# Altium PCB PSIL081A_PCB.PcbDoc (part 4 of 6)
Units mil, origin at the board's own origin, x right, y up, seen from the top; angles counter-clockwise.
Board outline 14000 x 8000 mil, 10 copper layers (Top Layer, Signal Layer 1, Signal Layer 2, Signal Layer 3, Signal Layer 4, Signal Layer 5, Signal Layer 6, Signal Layer 7, Signal Layer 8, Bottom Layer), stack 60.9 mil thick; 433 components, 510 nets, 1716 pads, 590 vias.
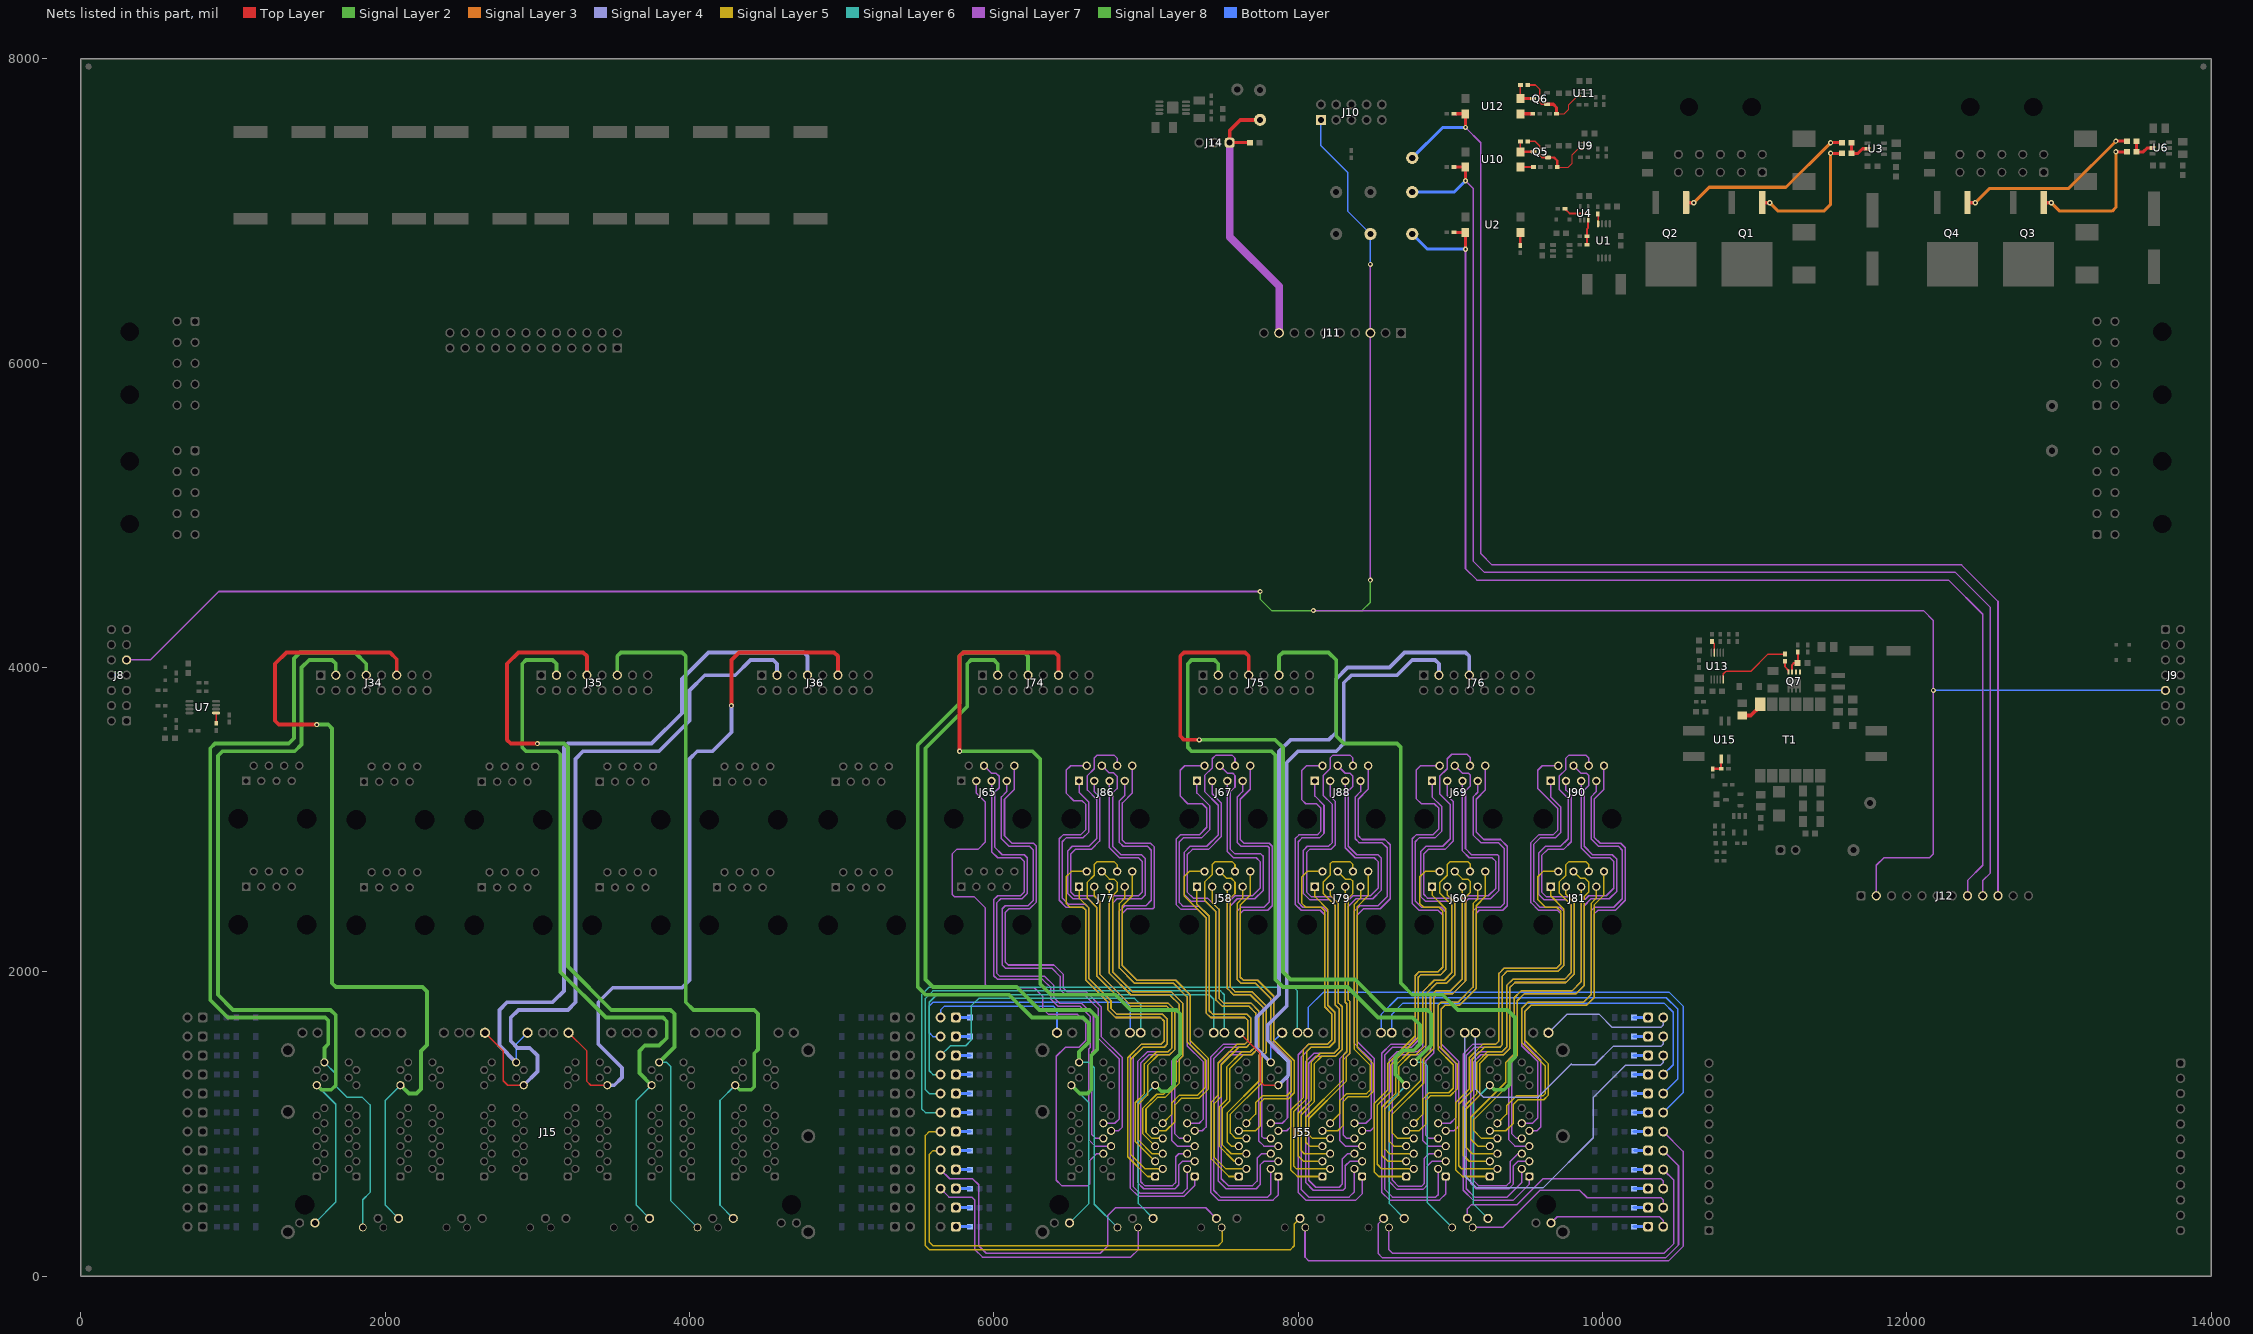
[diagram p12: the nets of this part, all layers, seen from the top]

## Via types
v1: diameter 34, hole 16, Top Layer to Bottom Layer, 429 vias
v2: diameter 26, hole 8, Top Layer to Bottom Layer, 156 vias
v3: diameter 19.68, hole 7.87, Top Layer to Bottom Layer, 5 vias

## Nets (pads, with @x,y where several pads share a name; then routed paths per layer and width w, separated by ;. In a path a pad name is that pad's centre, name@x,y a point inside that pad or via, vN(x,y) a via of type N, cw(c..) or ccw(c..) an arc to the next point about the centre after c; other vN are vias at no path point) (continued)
NetJ55_B4: J55.B4 J65.3 | length 4186.6
  Signal Layer 7 w10: J65.3@5885,3255 5885,3175 5945,3115 5945,2855 5895,2805 5755,2805 5725,2775 5725,2510 5740,2495 5870,2495 5945,2420 5945,1915 5965,1895 6265,1895 6320,1840 6320,1760 6360,1720 6550,1720 6605,1665 6605,1550 6560,1505 6470,1505 6410,1445 6410,630 6445,595 6620,595 6630,605 6630,760 6674.96,804.96 J55.B4@6720.16,804.96
NetJ55_B5: J55.B5 J65.5 | length 3394.1
  Signal Layer 7 w10: J65.5@5985,3255 5985,2790 6025,2750 6175,2750 6200,2725 6200,2525 6175,2500 6025,2500 6000,2475 6000,1975 6025,1950 6320,1950 6375,1895 6375,1820 6420,1775 6565,1775 6635,1705 6635,1504.72 6625.28,1495 6625.28,894.72 6665,855 6770.12,855 J55.B5@6770.16,854.96
NetJ55_B6: J55.B6 J65.4 | length 3445.7
  Signal Layer 7 w10: J65.4@5935,3355 5985,3305 6015,3305 6035,3285 6035,3210 6005,3180 6005,2820 6055,2770 6200,2770 6220,2750 6220,2515 6185,2480 6045,2480 6020,2455 6020,1990 6040,1970 6335,1970 6395,1910 6395,1830 6430,1795 6575,1795 6655,1715 6655,1485 6645,1475 6645,930 6670.04,904.96 J55.B6@6720.16,904.96
NetJ55_B7: J55.B7 J65.8 | length 3388
  Signal Layer 7 w10: J65.8@6135,3355 6135,3200 6070,3135 6070,2895 6120,2845 6260,2845 6280,2825 6280,2460 6235,2415 6100,2415 6075,2390 6075,2065 6095,2045 6395,2045 6455,1985 6455,1895 6480,1870 6605,1870 6705,1770 6705,1575 6845,1435 6845,980 6819.96,954.96 J55.B7@6770.16,954.96
NetJ55_B8: J55.B8 J65.7 | length 3261.5
  Signal Layer 7 w10: J65.7@6085,3255 6085,3185 6050,3150 6050,2875 6100,2825 6235,2825 6260,2800 6260,2470 6225,2435 6075,2435 6055,2415 6055,2045 6075,2025 6380,2025 6435,1970 6435,1885 6470,1850 6595,1850 6685,1760 6685,1565 6825,1425 6825,1035 6795,1005 J55.B8@6720.16,1004.96 J55.B8@6720.16,1004.96
NetJ55_B15: J55.B15 J66.2 | length 985.9
  Bottom Layer w10: J66.2@5650,1700 5650,1750 5675,1775 6390,1775 6415.04,1749.96 J55.B15@6415.04,1599.84
NetJ55_B18: J55.B18 J71.2 | length 1776.2
  Bottom Layer w10: J71.2@5650,1575 5600,1575 5575,1600 5575,1775 5600,1800 6870,1800 6895,1775 J55.B18@6894.96,1599.84 J55.B18@6894.96,1599.84
NetJ55_C1: J55.C1 J77.2 | length 2888.6
  Signal Layer 5 w10: J77.2@6610,2660 6510,2660 6475,2625 6475,2450 6500,2425 6585,2425 6605,2405 6605,1945 6750,1800 6750,1750 6800,1700 7095,1700 7120,1675 7120,1545 7100,1525 6970,1525 6880,1435 6880,785 7010,655 J55.C1@7059.92,654.96 J55.C1@7059.92,654.96
NetJ55_C2: J55.C2 J77.1 | length 2606.7
  Signal Layer 5 w10: J77.1@6560,2560 6560,2485 6625,2420 6625,1955 6770,1810 6770,1760 6810,1720 7110,1720 7140,1690 7140,1525 7120,1505 6980,1505 6900,1425 6900,800 6995.04,704.96 J55.C2@7109.92,704.96
NetJ55_C3: J55.C3 J77.6 | length 2759.6
  Signal Layer 5 w10: J77.6@6810,2660 6810,2705 6790,2725 6680,2725 6660,2705 6660,2635 6615,2590 6615,2485 6675,2425 6675,1975 6875,1775 7135,1775 7170,1740 7170,1500 7145,1475 7070,1475 6990,1395 6990,1199.94 6930,1139.94 6930,884.88 J55.C3@7059.92,754.96
NetJ55_C4: J55.C4 J77.3 | length 2377.4
  Signal Layer 5 w10: J77.3@6660,2560 6660,2500 6695,2465 6695,1985 6885,1795 7145,1795 7190,1750 7190,1490 7155,1455 7080,1455 7010,1385 7010,1190 6950,1130 6950,895 7040.04,804.96 J55.C4@7109.92,804.96
NetJ55_C5: J55.C5 J77.5 | length 2203.8
  Signal Layer 5 w10: J77.5@6760,2560 6760,1990 6900,1850 7155,1850 7220,1785 7220,1465 7200,1445 7200,1280 7115,1195 7070,1195 6980,1105 6980,934.88 J55.C5@7059.92,854.96
NetJ55_C6: J55.C6 J77.4 | length 2381.5
  Signal Layer 5 w10: J77.4@6710,2660 6760,2610 6790,2610 6810,2590 6810,2530 6780,2500 6780,2000 6910,1870 7165,1870 7240,1795 7240,1445 7220,1425 7220,1270 7125,1175 7075,1175 7000,1100 7000,945 7040.04,904.96 J55.C6@7109.92,904.96
NetJ55_C7: J55.C7 J77.8 | length 2368.8
  Signal Layer 5 w10: J77.8@6910,2660 6910,2500 6845,2435 6845,2040 6940,1945 7195,1945 7290,1850 7290,1550 7410,1430 7410,1230 7350,1170 7235,1170 7190,1125 7190,1015 7129.96,954.96 J55.C7@7059.92,954.96
NetJ55_C8: J55.C8 J77.7 | length 2139.2
  Signal Layer 5 w10: J77.7@6860,2560 6860,2485 6825,2450 6825,2025 6925,1925 7180,1925 7270,1835 7270,1540 7390,1420 7390,1240 7340,1190 7220,1190 7170,1140 7170,1065.04 J55.C8@7109.92,1004.96
NetJ55_C15: J55.C15 J78.2 | length 1843.5
  Signal Layer 7 w10: J78.2@5650,575 5705,520 5855,520 5875,500 5875,175 5925,125 6900,125 6950,175 6950,317.24 J55.C15@6947.32,319.92
NetJ55_C18: J55.C18 J83.2 | length 2544.9
  Signal Layer 7 w10: J83.2@5650,700 5710,640 5860,640 5900,600 5900,200 5950,150 6700,150 6750,200 6750,400 6800,450 7392.05,450 J55.C18@7462.28,379.76
NetJ55_D1: J55.D1 J86.2 | length 4347.5
  Signal Layer 7 w10: J86.2@6610,3355 6505,3355 6475,3325 6475,3175 6525,3125 6580,3125 6605,3100 6605,2935 6570,2900 6455,2900 6430,2875 6430,2470 6475,2425 6585,2425 6605,2405 6605,1945 6750,1800 6750,1750 6800,1700 7095,1700 7120,1675 7120,1545 7100,1525 6970,1525 6895,1450 6895,580 6950,525 7250,525 7320,595 7320,654.8 J55.D1@7320.16,654.96
NetJ55_D2: J55.D2 J86.1 | length 4046.1
  Signal Layer 7 w10: J86.1@6560,3255 6560,3180 6625,3115 6625,2920 6585,2880 6475,2880 6450,2855 6450,2485 6490,2445 6600,2445 6625,2420 6625,1955 6770,1810 6770,1760 6810,1720 7110,1720 7140,1690 7140,1525 7120,1505 6980,1505 6915,1440 6915,590 6960,545 7240,545 7270.16,575.16 J55.D2@7270.16,704.96
NetJ55_D3: J55.D3 J86.6 | length 4402.5
  Signal Layer 7 w10: J86.6@6810,3355 6810,3405 6790,3425 6680,3425 6660,3405 6660,3335 6615,3290 6615,3195 6675,3135 6675,2875 6625,2825 6515,2825 6485,2795 6485,2515 6520,2480 6620,2480 6675,2425 6675,1975 6875,1775 7135,1775 7170,1740 7170,1500 7145,1475 7010,1475 6945,1410 6945,615 6985,575 7190,575 7215,600 7215,730 7240,755 7320.12,755 J55.D3@7320.16,754.96
NetJ55_D4: J55.D4 J86.3 | length 3976
  Signal Layer 7 w10: J86.3@6660,3255 6660,3185 6695,3150 6695,2860 6640,2805 6535,2805 6505,2775 6505,2525 6530,2500 6660,2500 6695,2465 6695,1985 6885,1795 7145,1795 7190,1750 7190,1490 7155,1455 7020,1455 6965.14,1400.14 6965.14,620.14 6990.28,595 7175,595 7195,615 7195,785 7214.96,804.96 J55.D4@7270.16,804.96
NetJ55_D5: J55.D5 J86.5 | length 3238.3
  Signal Layer 7 w10: J86.5@6760,3255 6760,2815 6825,2750 6950,2750 6975,2725 6975,2525 6950,2500 6785,2500 6760,2475 6760,1990 6900,1850 7155,1850 7220,1785 7220,1465 7170,1415 7170,890 7205,855 7320.12,855 J55.D5@7320.16,854.96
NetJ55_D6: J55.D6 J86.4 | length 3295.6
  Signal Layer 7 w10: J86.4@6710,3355 6755,3310 6785,3310 6810,3285 6810,3205 6780,3175 6780,2825 6835,2770 6970,2770 6995,2745 6995,2505 6970,2480 6810,2480 6780,2450 6780,2000 6910,1870 7165,1870 7240,1795 7240,1445 7190,1395 7190,935 7220.04,904.96 J55.D6@7270.16,904.96
NetJ55_D7: J55.D7 J86.8 | length 3234.5
  Signal Layer 7 w10: J86.8@6910,3355 6910,3175 6845,3110 6845,2865 6865,2845 7030,2845 7055,2820 7055,2425 7045,2415 6875,2415 6845,2385 6845,2040 6940,1945 7195,1945 7290,1850 7290,1525 7395,1420 7395,980 7369.96,954.96 J55.D7@7320.16,954.96
NetJ55_D8: J55.D8 J86.7 | length 3081.6
  Signal Layer 7 w10: J86.7@6860,3255 6860,3160 6825,3125 6825,2850 6850,2825 7010,2825 7035,2800 7035,2470 7000,2435 6860,2435 6825,2400 6825,2025 6925,1925 7180,1925 7270,1835 7270,1515 7375,1410 7375,1030 7349.96,1004.96 J55.D8@7270.16,1004.96
NetJ55_D15: J55.D15 J87.2 | length 1803.9
  Signal Layer 6 w10: J87.2@5650,1450 5715,1515 5815,1515 5850,1550 5850,1775 5900,1825 6925,1825 6965,1785 J55.D15@6965.04,1599.84 J55.D15@6965.04,1599.84
NetJ55_D18: J55.D18 J92.2 | length 2658.7
  Signal Layer 6 w10: J92.2@5650,1325 5600,1325 5575,1350 5575,1800 5625,1850 7415,1850 7445,1820 J55.D18@7444.96,1599.84 J55.D18@7444.96,1599.84
NetJ55_E1: J55.E1 J58.2 | length 2666.5
  Signal Layer 5 w10: J58.2@7385,2660 7285,2660 7250,2625 7250,2500 7395,2355 7395,1730 7425,1700 7650,1700 7670,1680 7670,1545 7650,1525 7600,1525 7475,1400 7475,1190 7430,1145 7430,770 7545,655 J55.E1@7609.92,654.96 J55.E1@7609.92,654.96
NetJ55_E2: J55.E2 J58.1 | length 2428.6
  Signal Layer 5 w10: J58.1@7335,2560 7335,2445 7415,2365 7415,1745 7440,1720 7665,1720 7690,1695 7690,1535 7660,1505 7610,1505 7495,1390 7495,1180 7450,1135 7450,780 7525.04,704.96 J55.E2@7659.92,704.96
NetJ55_E3: J55.E3 J58.6 | length 2626.5
  Signal Layer 5 w10: J58.6@7585,2660 7585,2705 7565,2725 7455,2725 7435,2705 7435,2640 7385,2590 7385,2470 7460,2395 7460,1815 7500,1775 7675,1775 7720,1730 7720,1510 7685,1475 7630,1475 7530,1375 7530,1160 7480,1110 7480,855 7580,755 J55.E3@7609.92,754.96 J55.E3@7609.92,754.96
NetJ55_E4: J55.E4 J58.3 | length 2242.8
  Signal Layer 5 w10: J58.3@7435,2560 7435,2455 7480,2410 7480,1825 7510,1795 7690,1795 7740,1745 7740,1500 7695,1455 7640.6,1455 7550.6,1365 7550.6,1150.6 7500,1100 7500,865 7560.04,804.96 J55.E4@7659.92,804.96
NetJ55_E5: J55.E5 J58.5 | length 2024.4
  Signal Layer 5 w10: J58.5@7535,2560 7535,1890 7575,1850 7685,1850 7770,1765 7770,1480 7745,1455 7745,1285 7535,1075 7535,880 7560,855 J55.E5@7609.92,854.96 J55.E5@7609.92,854.96
NetJ55_E6: J55.E6 J58.4 | length 2170
  Signal Layer 5 w10: J58.4@7485,2660 7530,2615 7560,2615 7585,2590 7585,2515 7555,2485 7555,1900 7585,1870 7695,1870 7790,1775 7790,1470 7765,1445 7765,1275 7555,1065 7555,940 7590.04,904.96 J55.E6@7659.92,904.96
NetJ55_E7: J55.E7 J58.8 | length 2244.1
  Signal Layer 5 w10: J55.E7@7609.92,954.96 7719.96,954.96 7750,985 7750,1140 7775,1165 7935,1165 7975,1205 7975,1415 7840,1550 7840,1840 7735,1945 7640,1945 7620,1965 7620,2440 7685,2505 J58.8@7685,2660
NetJ55_E8: J55.E8 J58.7 | length 1988.2
  Signal Layer 5 w10: J58.7@7635,2560 7635,2485 7600,2450 7600,1950 7625,1925 7720,1925 7820,1825 7820,1545 7955,1410 7955,1215 7925,1185 7765,1185 7720,1140 7720,1065.04 J55.E8@7659.92,1004.96
NetJ55_E15: J55.E15 J59.2 | length 2702.1
  Signal Layer 5 w10: J59.2@5650,825 5600,825 5575,800 5575,225 5600,200 7475,200 7500,225 7500,317.24 J55.E15@7497.32,319.92
NetJ55_E18: J55.E18 J63.2 | length 3476.3
  Signal Layer 5 w10: J63.2@5650,950 5575,950 5550,925 5550,200 5575,175 7950,175 7975,200 7975,342.48 J55.E18@8012.28,379.76
NetJ55_F1: J55.F1 J67.2 | length 4406.3
  Signal Layer 7 w10: J67.2@7385,3355 7255,3355 7225,3325 7225,3155 7275,3105 7370,3105 7400,3075 7400,2950 7350,2900 7225,2900 7200,2875 7200,2440 7230,2410 7340,2410 7395,2355 7395,1730 7425,1700 7650,1700 7670,1680 7670,1545 7650,1525 7510,1525 7425,1440 7425,550 7475,500 7835,500 7870,535 7870,654.8 J55.F1@7870.16,654.96
NetJ55_F2: J55.F2 J67.1 | length 4016.8
  Signal Layer 7 w10: J67.1@7335,3255 7335,3175 7420,3090 7420,2935 7365,2880 7245,2880 7220,2855 7220,2455 7245,2430 7350,2430 7415,2365 7415,1745 7440,1720 7665,1720 7690,1695 7690,1535 7660,1505 7520,1505 7445,1430 7445,565 7490,520 7800,520 7820.16,540.16 J55.F2@7820.16,704.96
NetJ55_F3: J55.F3 J67.6 | length 4312.2
  Signal Layer 7 w10: J67.6@7585,3355 7585,3405 7565,3425 7460,3425 7435,3400 7435,3340 7385,3290 7385,3185 7475,3095 7475,2900 7400,2825 7290,2825 7250,2785 7250,2510 7295,2465 7390,2465 7460,2395 7460,1815 7500,1775 7675,1775 7720,1730 7720,1510 7685,1475 7545,1475 7475,1405 7475,625 7525,575 7725,575 7750,600 7750,730 7775,755 7870.12,755 J55.F3@7870.16,754.96
NetJ55_F4: J55.F4 J67.3 | length 3852.5
  Signal Layer 7 w10: J67.3@7435,3255 7435,3170 7495,3110 7495,2890 7410,2805 7305,2805 7270,2770 7270,2525 7310,2485 7405,2485 7480,2410 7480,1825 7510,1795 7690,1795 7740,1745 7740,1500 7695,1455 7555,1455 7495,1395 7495,640 7540,595 7700,595 7730,625 7730,775 7759.96,804.96 J55.F4@7820.16,804.96
NetJ55_F5: J55.F5 J67.5 | length 3017.2
  Signal Layer 7 w10: J67.5@7535,3255 7535,2790 7575,2750 7725,2750 7750,2725 7750,2550 7700,2500 7585,2500 7535,2450 7535,1890 7575,1850 7685,1850 7770,1765 7770,1480 7740,1450 7740,890 7775,855 7870.12,855 J55.F5@7870.16,854.96
NetJ55_F6: J55.F6 J67.4 | length 3095
  Signal Layer 7 w10: J67.4@7485,3355 7535,3305 7570,3305 7585,3290 7585,3215 7555,3185 7555,2805 7585,2775 7755,2775 7770,2760 7770,2535 7715,2480 7600,2480 7555,2435 7555,1900 7585,1870 7695,1870 7790,1775 7790,1470 7760,1440 7760,920 7775.04,904.96 J55.F6@7820.16,904.96
NetJ55_F7: J55.F7 J67.8 | length 3048.8
  Signal Layer 7 w10: J67.8@7685,3355 7685,3200 7620,3135 7620,2870 7645,2845 7810,2845 7830,2825 7830,2435 7800,2405 7640,2405 7620,2385 7620,1965 7640,1945 7735,1945 7840,1840 7840,1530 7950,1420 7950,980 7924.96,954.96 J55.F7@7870.16,954.96
NetJ55_F8: J55.F8 J67.7 | length 2910.5
  Signal Layer 7 w10: J67.7@7635,3255 7635,3185 7600,3150 7600,2850 7625,2825 7800,2825 7810,2815 7810,2460 7775,2425 7625,2425 7600,2400 7600,1950 7625,1925 7720,1925 7820,1825 7820,1515 7930,1405 7930,1040 7895,1005 J55.F8@7820.16,1004.96 J55.F8@7820.16,1004.96
NetJ55_F15: J55.F15 J68.2 | length 2956.6
  Signal Layer 6 w10: J68.2@5650,1200 5575,1200 5550,1225 5550,1825 5600,1875 7490,1875 7515.04,1849.96 J55.F15@7515.04,1599.84
NetJ55_F18: J55.F18 J72.2 | length 3661.6
  Signal Layer 6 w10: J72.2@5650,1075 5550,1075 5525,1100 5525,1850 5575,1900 7970,1900 7995,1875 J55.F18@7994.96,1599.84 J55.F18@7994.96,1599.84
NetJ55_G1: J55.G1 J79.2 | length 2627.3
  Signal Layer 5 w10: J55.G1@8159.92,654.96 J55.G1@8159.92,654.96 7995,655 7950,700 7950,1090 8035,1175 8035,1490 8070,1525 8194.72,1525 8220,1550.28 8220,1725 8175,1770 8175,2400 8150,2425 8050,2425 8025,2450 8025,2625 8060,2660 J79.2@8160,2660
NetJ55_G2: J55.G2 J79.1 | length 2319.2
  Signal Layer 5 w10: J79.1@8110,2560 8110,2495 8195,2410 8195,1780 8240,1735 8240,1540 8205,1505 8085,1505 8055,1475 8055,1165 7970,1080 7970,725 7990.04,704.96 J55.G2@8209.92,704.96
NetJ55_G3: J55.G3 J79.6 | length 2530.6
  Signal Layer 5 w10: J55.G3@8159.92,754.96 J55.G3@8159.92,754.96 8035,755 8000,790 8000,1070 8085,1155 8085,1405 8145,1465 8235,1465 8270,1500 8270,1755 8245,1780 8245,2435 8165,2515 8165,2590 8210,2635 8210,2710 8225,2725 8340,2725 8360,2705 J79.6@8360,2660
NetJ55_G4: J55.G4 J79.3 | length 2130.9
  Signal Layer 5 w10: J55.G4@8209.92,804.96 8040.04,804.96 8020,825 8020,1060 8105,1145 8105,1395 8155,1445 8245,1445 8290,1490 8290,1770 8265,1795 8265,2450 8210,2505 J79.3@8210,2560
NetJ55_G5: J55.G5 J79.5 | length 1916.3
  Signal Layer 5 w10: J55.G5@8159.92,854.96 J55.G5@8159.92,854.96 8075,855 8050,880 8050,1045 8295,1290 8295,1450 8320,1475 8320,1790 8310,1800 J79.5@8310,2560
NetJ55_G6: J55.G6 J79.4 | length 2070.6
  Signal Layer 5 w10: J55.G6@8209.92,904.96 8095.04,904.96 8070,930 8070,1035 8315,1280 8315,1440 8340,1465 8340,1805 8330,1815 8330,2485 8360,2515 8360,2595 8345,2610 8310,2610 J79.4@8260,2660
NetJ55_G7: J55.G7 J79.8 | length 2051.1
  Signal Layer 5 w10: J55.G7@8159.92,954.96 8159.96,955 8260,955 8295,990 8295,1145 8330,1180 8460,1180 8495,1215 8495,1395 8390,1500 8390,2430 8460,2500 J79.8@8460,2660
NetJ55_G8: J55.G8 J79.7 | length 1801.1
  Signal Layer 5 w10: J55.G8@8209.92,1004.96 8275,1070.04 8275,1155 8320,1200 8450,1200 8475,1225 8475,1385 8370,1490 8370,2445 8410,2485 J79.7@8410,2560
NetJ55_G15: J55.G15 J80.2 | length 3539.4
  Signal Layer 7 w10: J55.G15@8047.32,319.92 8045,317.6 8045,125 8070,100 10435,100 10530,195 10530,820 J80.2@10400,950
NetJ55_G18: J55.G18 J84.2 | length 2929.3
  Signal Layer 7 w10: J55.G18@8562.28,379.76 8525,342.48 8525,150 8555,120 10415,120 10500,205 10500,725 J84.2@10400,825
NetJ55_H1: J55.H1 J88.2 | length 4065
  Signal Layer 7 w10: J88.2@8160,3355 8055,3355 8025,3325 8025,3130 8050,3105 8120,3105 8150,3075 8150,2925 8125,2900 8005,2900 7980,2875 7980,2445 8020,2405 8145,2405 8175,2375 8175,1770 8220,1725 8220,1550.28 8194.72,1525 8070,1525 8000,1455 8000,550 8050,500 8380,500 8420,540 8420,654.8 J55.H1@8420.16,654.96
NetJ55_H2: J55.H2 J88.1 | length 3722.8
  Signal Layer 7 w10: J88.1@8110,3255 8110,3155 8170,3095 8170,2910 8140,2880 8025,2880 8000,2855 8000,2455 8030,2425 8165,2425 8195,2395 8195,1780 8240,1735 8240,1540 8205,1505 8085,1505 8020,1440 8020,570 8070,520 8335,520 8370.16,555.16 J55.H2@8370.16,704.96
NetJ55_H3: J55.H3 J88.6 | length 4106.1
  Signal Layer 7 w10: J88.6@8360,3355 8360,3405 8340,3425 8230,3425 8210,3405 8210,3335 8165,3290 8165,3160 8225,3100 8225,2850 8200,2825 8060,2825 8035,2800 8035,2515 8075,2475 8205,2475 8245,2435 8245,1780 8270,1755 8270,1500 8235,1465 8105,1465 8050,1410 8050,615 8100,565 8295,565 8310,580 8310,725 8340,755 8420.12,755 J55.H3@8420.16,754.96
NetJ55_H4: J55.H4 J88.3 | length 3650.5
  Signal Layer 7 w10: J88.3@8210,3255 8210,3155 8245,3120 8245,2835 8215,2805 8075,2805 8055,2785 8055,2525 8085,2495 8220,2495 8265,2450 8265,1795 8290,1770 8290,1490 8245,1445 8115,1445 8070,1400 8070,630 8115,585 8270,585 8290,605 8290,770 8324.96,804.96 J55.H4@8370.16,804.96
NetJ55_H5: J55.H5 J88.5 | length 2866.2
  Signal Layer 7 w10: J88.5@8310,3255 8310,2815 8375,2750 8500,2750 8525,2725 8525,2550 8475,2500 8360,2500 8310,2450 8310,1800 8320,1790 8320,1475 8275,1430 8275,890 8310,855 8420.12,855 J55.H5@8420.16,854.96
NetJ55_H6: J55.H6 J88.4 | length 2929.3
  Signal Layer 7 w10: J88.4@8260,3355 8310,3305 8340,3305 8360,3285 8360,3220 8330,3190 8330,2825 8385,2770 8525,2770 8545,2750 8545,2535 8490,2480 8380,2480 8330,2430 8330,1815 8340,1805 8340,1465 8295,1420 8295,930 8320.04,904.96 J55.H6@8370.16,904.96
NetJ55_H7: J55.H7 J88.8 | length 2866
  Signal Layer 7 w10: J55.H7@8420.16,954.96 8474.96,954.96 8500,980 8500,1430 8390,1540 8390,2375 8430,2415 8540,2415 8605,2480 8605,2835 8570,2870 8420,2870 8395,2895 8395,3135 8460,3200 J88.8@8460,3355
NetJ55_H8: J55.H8 J88.7 | length 2733.6
  Signal Layer 7 w10: J55.H8@8370.16,1004.96 8444.96,1004.96 8480,1040 8480,1420 8370,1530 8370,2400 8405,2435 8525,2435 8585,2495 8585,2815 8550,2850 8400,2850 8375,2875 8375,3150 8410,3185 J88.7@8410,3255
NetJ55_H15: J55.H15 J89.2 | length 3462.7
  Bottom Layer w10: J55.H15@8065.04,1599.84 J55.H15@8065.04,1599.84 8065,1765 8165,1865 10440,1865 10530,1775 10530,1205 J89.2@10400,1075
NetJ55_H18: J55.H18 J93.2 | length 2741.2
  Bottom Layer w10: J55.H18@8544.96,1599.84 8544.96,1719.96 8655,1830 10420,1830 10495,1755 10495,1295 J93.2@10400,1200
NetJ55_I1: J55.I1 J60.2 | length 2687.2
  Signal Layer 5 w10: J55.I1@8709.92,654.96 J55.I1@8709.92,654.96 8530,655 8500,685 8500,1135 8590,1225 8590,1400 8770,1580 8770,1975 8795,2000 8920,2000 8950,2030 8950,2400 8925,2425 8825,2425 8800,2450 8800,2625 8835,2660 J60.2@8930,2660
NetJ55_I2: J55.I2 J60.1 | length 2377.2
  Signal Layer 5 w10: J55.I2@8759.92,704.96 8550.04,704.96 8520,735 8520,1125 8610,1215 8610,1390 8790,1570 8790,1965 8805,1980 8935,1980 8970,2015 8970,2415 8880,2505 J60.1@8880,2560
NetJ55_I3: J55.I3 J60.6 | length 2601
  Signal Layer 5 w10: J55.I3@8709.92,754.96 J55.I3@8709.92,754.96 8590,755 8550,795 8550,1110 8640,1200 8640,1385 8730,1475 8760,1475 8820,1535 8820,1870 8895,1945 8960,1945 9010,1995 9010,2440 8930,2520 8930,2585 8980,2635 8980,2705 9000,2725 9115,2725 9130,2710 J60.6@9130,2660
NetJ55_I4: J55.I4 J60.3 | length 2197.2
  Signal Layer 5 w10: J55.I4@8759.92,804.96 8600.04,804.96 8570,835 8570,1100 8660,1190 8660,1375 8740,1455 8775,1455 8840,1520 8840,1855 8910,1925 8975,1925 9030,1980 9030,2455 8980,2505 J60.3@8980,2560
NetJ55_I5: J55.I5 J60.5 | length 2051.8
  Signal Layer 5 w10: J55.I5@8709.92,854.96 J55.I5@8709.92,854.96 8630,855 8600,885 8600,1080 8805,1285 8805,1440 8870,1505 8870,1840 8905,1875 9000,1875 9080,1955 J60.5@9080,2560
NetJ55_I6: J55.I6 J60.4 | length 2206.2
  Signal Layer 5 w10: J55.I6@8759.92,904.96 8655.04,904.96 8620,940 8620,1065 8825,1270 8825,1430 8890,1495 8890,1830 8915,1855 9015,1855 9100,1940 9100,2490 9130,2520 9130,2595 9115,2610 9080,2610 J60.4@9030,2660
NetJ55_I7: J55.I7 J60.8 | length 2189.1
  Signal Layer 5 w10: J55.I7@8709.92,954.96 8794.96,954.96 8840,1000 8840,1155 8870,1185 9000,1185 9045,1230 9045,1395 8940,1500 8940,1755 8965,1780 9060,1780 9170,1890 9170,2435 9230,2495 J60.8@9230,2660
NetJ55_I8: J55.I8 J60.7 | length 1952.5
  Signal Layer 5 w10: J55.I8@8759.92,1004.96 8820,1065.04 8820,1165 8860,1205 8990,1205 9020,1235 9020,1390 8920,1490 8920,1780 8940,1800 9050,1800 9150,1900 9150,2450 9180,2480 J60.7@9180,2560
NetJ55_I15: J55.I15 J61.2 | length 2572.2
  Signal Layer 7 w10: J55.I15@8597.32,319.92 8595,317.6 8595,175 8620,150 10405,150 10470,215 10470,630 J61.2@10400,700
NetJ55_I18: J55.I18 J64.2 | length 1488.3
  Signal Layer 7 w10: J55.I18@9112.28,379.76 9112.28,442.28 9140,470 9440,470 9610,640 10385,640 10400,625 J64.2@10400,575
NetJ55_J1: J55.J1 J69.2 | length 4231.8
  Signal Layer 7 w10: J69.2@8930,3355 8805,3355 8775,3325 8775,3140 8810,3105 8895,3105 8925,3075 8925,2940 8885,2900 8775,2900 8750,2875 8750,2450 8795,2405 8920,2405 8950,2375 8950,2030 8920,2000 8795,2000 8770,1975 8770,1560 8735,1525 8610,1525 8550,1465 8550,550 8600,500 8930,500 8970,540 8970,654.8 J55.J1@8970.16,654.96
NetJ55_J2: J55.J2 J69.1 | length 3866.9
  Signal Layer 7 w10: J69.1@8880,3255 8880,3150 8945,3085 8945,2925 8900,2880 8795,2880 8770,2855 8770,2465 8810,2425 8940,2425 8970,2395 8970,2015 8935,1980 8805,1980 8790,1965 8790,1550 8745,1505 8620,1505 8570,1455 8570,570 8620,520 8905,520 8920.16,535.16 J55.J2@8920.16,704.96
NetJ55_J3: J55.J3 J69.6 | length 4201.1
  Signal Layer 7 w10: J55.J3@8970.16,754.96 8970.12,755 8880,755 8850,725 8850,600 8820,570 8650,570 8600,620 8600,1425 8650,1475 8785,1475 8820,1510 8820,1870 8895,1945 8960,1945 9010,1995 9010,2440 8985,2465 8835,2465 8805,2495 8805,2790 8840,2825 8950,2825 9000,2875 9000,3100 8930,3170 8930,3285 8980,3335 8980,3400 9010,3430 9110,3430 9130,3410 J69.6@9130,3355
NetJ55_J4: J55.J4 J69.3 | length 3749.9
  Signal Layer 7 w10: J55.J4@8920.16,804.96 8859.96,804.96 8830,775 8830,610 8810,590 8660,590 8620,630 8620,1416.54 8658.46,1455 8795,1455 8840,1500 8840,1855 8910,1925 8975,1925 9030,1980 9030,2455 9000,2485 8850,2485 8825,2510 8825,2775 8855,2805 8965,2805 9020,2860 9020,3120 8980,3160 J69.3@8980,3255
NetJ55_J5: J55.J5 J69.5 | length 3048.1
  Signal Layer 7 w10: J55.J5@8970.16,854.96 8855.04,854.96 8820,890 8820,1425 8870,1475 8870,1840 8905,1875 9000,1875 9080,1955 9080,2475 9105,2500 9250,2500 9300,2550 9300,2725 9275,2750 9125,2750 9080,2795 J69.5@9080,3255
NetJ55_J6: J55.J6 J69.4 | length 3128.8
  Signal Layer 7 w10: J55.J6@8920.16,904.96 8860.04,904.96 8840,925 8840,1415 8890,1465 8890,1830 8915,1855 9015,1855 9100,1940 9100,2460 9120,2480 9265,2480 9320,2535 9320,2760 9310,2770 9140,2770 9100,2810 9100,3190 9130,3220 9130,3295 9120,3305 9080,3305 J69.4@9030,3355
NetJ55_J7: J55.J7 J69.8 | length 3015.8
  Signal Layer 7 w10: J55.J7@8970.16,954.96 9024.96,954.96 9055,985 9055,1410 8940,1525 8940,1755 8965,1780 9060,1780 9170,1890 9170,2385 9190,2405 9345,2405 9375,2435 9375,2825 9330,2870 9220,2870 9170,2920 9170,3135 9230,3195 J69.8@9230,3355
NetJ55_J8: J55.J8 J69.7 | length 2892.1
  Signal Layer 7 w10: J55.J8@8920.16,1004.96 8999.96,1004.96 9035,1040 9035,1400 8920,1515 8920,1780 8940,1800 9050,1800 9150,1900 9150,2400 9175,2425 9330,2425 9355,2450 9355,2810 9315,2850 9200,2850 9150,2900 9150,3150 9180,3180 J69.7@9180,3255
NetJ55_J15: J55.J15 J70.2 | length 2463
  Bottom Layer w10: J55.J15@8615.04,1599.84 8615.04,1719.96 8615,1720 8690,1795 10405,1795 10465,1735 10465,1390 J70.2@10400,1325
NetJ55_J18: J55.J18 J73.2 | length 2820
  Signal Layer 4 w10: J55.J18@9094.96,1599.84 9094.96,660.04 9175,580 9610,580 9940,910 9940,1175 10150,1385 10380,1385 10400,1405 J73.2@10400,1450
  Bottom Layer w10: J55.J18@9094.96,1599.84 J55.J18@9094.96,1599.84
NetJ55_K1: J55.K1 J81.2 | length 2961.8
  Signal Layer 5 w10: J55.K1@9259.92,654.96 J55.K1@9259.92,654.96 9080,655 9035,700 9035,1140 9125,1230 9125,1435 9215,1525 9300,1525 9320,1545 9320,1990 9355,2025 9700,2025 9725,2050 9725,2400 9700,2425 9625,2425 9575,2475 9575,2625 9610,2660 J81.2@9710,2660
NetJ55_K2: J55.K2 J81.1 | length 2674.1
  Signal Layer 5 w10: J55.K2@9309.92,704.96 9075.04,704.96 9055,725 9055,1130 9145,1220 9145,1425 9225,1505 9325,1505 9340,1520 9340,1970 9375,2005 9710,2005 9745,2040 9745,2415 9660,2500 J81.1@9660,2560
NetJ55_K3: J55.K3 J81.6 | length 2913.8
  Signal Layer 5 w10: J55.K3@9259.92,754.96 J55.K3@9259.92,754.96 9125,755 9085,795 9085,1110 9175,1200 9175,1405 9245,1475 9340,1475 9370,1505 9370,1910 9410,1950 9750,1950 9795,1995 9795,2440 9715,2520 9715,2590 9760,2635 9760,2705 9780,2725 9890,2725 9910,2705 J81.6@9910,2660
NetJ55_K4: J55.K4 J81.3 | length 2508.2
  Signal Layer 5 w10: J55.K4@9309.92,804.96 9145.04,804.96 9105,845 9105,1100 9195,1190 9195,1400 9250,1455 9350,1455 9390,1495 9390,1895 9425,1930 9760,1930 9815,1985 9815,2455 9760,2510 J81.3@9760,2560
NetJ55_K5: J55.K5 J81.5 | length 2300.1
  Signal Layer 5 w10: J55.K5@9259.92,854.96 J55.K5@9259.92,854.96 9180,855 9135,900 9135,1045 9365,1275 9365,1405 9420,1460 9420,1830 9465,1875 9800,1875 9860,1935 J81.5@9860,2560
NetJ55_K6: J55.K6 J81.4 | length 2451.5
  Signal Layer 5 w10: J55.K6@9309.92,904.96 9205.04,904.96 9155,955 9155,1030 9395,1270 9395,1405 9440,1450 9440,1810 9485,1855 9825,1855 9880,1910 9880,2495 9910,2525 9910,2590 9885,2615 9855,2615 J81.4@9810,2660
NetJ55_K7: J55.K7 J81.8 | length 2519.1
  Signal Layer 5 w10: J55.K7@9259.92,954.96 9364.96,954.96 9415,1005 9415,1130 9445,1160 9615,1160 9645,1190 9645,1395 9490,1550 9490,1740 9530,1780 9895,1780 9945,1830 9945,2440 10010,2505 J81.8@10010,2660
NetJ55_K8: J55.K8 J81.7 | length 2269
  Signal Layer 5 w10: J55.K8@9309.92,1004.96 9370,1065.04 9370,1120 9435,1185 9610,1185 9625,1200 9625,1380 9470,1535 9470,1760 9510,1800 9875,1800 9925,1850 9925,2450 9960,2485 J81.7@9960,2560
NetJ55_K15: J55.K15 J82.2 | length 1431.1
  Signal Layer 7 w10: J55.K15@9147.32,319.92 9344.92,319.92 9590,565 9850,565 9900,515 10385,515 10400,500 J82.2@10400,450
NetJ55_K18: J55.K18 J85.2 | length 804.3
  Signal Layer 7 w10: J55.K18@9662.68,349.84 9702.83,390 10375,390 10400,365 J85.2@10400,325
NetJ55_L1: J55.L1 J90.2 | length 4353.9
  Signal Layer 7 w10: J55.L1@9520.16,654.96 9520,654.8 9520,605 9415,500 9150,500 9085,565 9085,1460 9150,1525 9300,1525 9320,1545 9320,1990 9355,2025 9700,2025 9725,2050 9725,2385 9705,2405 9580,2405 9530,2455 9530,2850 9580,2900 9675,2900 9705,2930 9705,3075 9575,3205 9575,3325 9605,3355 J90.2@9710,3355
NetJ55_L2: J55.L2 J90.1 | length 4070.1
  Signal Layer 7 w10: J55.L2@9470.16,704.96 9470.16,615.16 9375,520 9160,520 9105,575 9105,1450 9160,1505 9325,1505 9340,1520 9340,1970 9375,2005 9710,2005 9745,2040 9745,2400 9720,2425 9590,2425 9550,2465 9550,2840 9590,2880 9690,2880 9725,2915 9725,3085 9660,3150 J90.1@9660,3255
NetJ55_L3: J55.L3 J90.6 | length 4473.3
  Signal Layer 7 w10: J55.L3@9520.16,754.96 9520.12,755 9445,755 9415,725 9415,605 9385,575 9170,575 9135,610 9135,1420 9190,1475 9340,1475 9370,1505 9370,1910 9410,1950 9750,1950 9795,1995 9795,2440 9760,2475 9615,2475 9580,2510 9580,2780 9625,2825 9725,2825 9775,2875 9775,3140 9715,3200 9715,3285 9760,3330 9760,3405 9780,3425 9890,3425 9910,3405 J90.6@9910,3355
NetJ55_L4: J55.L4 J90.3 | length 4011.9
  Signal Layer 7 w10: J55.L4@9470.16,804.96 9444.96,804.96 9395,755 9395,620 9370,595 9185,595 9155,625 9155,1410 9200,1455 9350,1455 9390,1495 9390,1895 9425,1930 9760,1930 9815,1985 9815,2455 9775,2495 9630,2495 9600,2525 9600,2765 9640,2805 9745,2805 9795,2855 9795,3160 9760,3195 J90.3@9760,3255
NetJ55_L5: J55.L5 J90.5 | length 3223.4
  Signal Layer 7 w10: J55.L5@9520.16,854.96 9520.12,855 9425,855 9385,895 9385,1425 9420,1460 9420,1830 9465,1875 9800,1875 9860,1935 9860,2450 9910,2500 10025,2500 10075,2550 10075,2725 10050,2750 9925,2750 9860,2815 J90.5@9860,3255
NetJ55_L6: J55.L6 J90.4 | length 3292.4
  Signal Layer 7 w10: J55.L6@9470.16,904.96 9435.04,904.96 9405,935 9405,1415 9440,1450 9440,1810 9485,1855 9825,1855 9880,1910 9880,2435 9925,2480 10045,2480 10095,2530 10095,2740 10065,2770 9935,2770 9880,2825 9880,3195 9910,3225 9910,3290 9895,3305 9860,3305 J90.4@9810,3355
NetJ55_L7: J55.L7 J90.8 | length 3249.2
  Signal Layer 7 w10: J55.L7@9520.16,954.96 9569.96,954.96 9595,980 9595,1420 9490,1525 9490,1740 9530,1780 9895,1780 9945,1830 9945,2380 9970,2405 10085,2405 10150,2470 10150,2815 10120,2845 9985,2845 9945,2885 9945,3135 10010,3200 J90.8@10010,3355
NetJ55_L8: J55.L8 J90.7 | length 3113.8
  Signal Layer 7 w10: J55.L8@9470.16,1004.96 9539.96,1004.96 9575,1040 9575,1410 9470,1515 9470,1760 9510,1800 9875,1800 9925,1850 9925,2400 9950,2425 10075,2425 10130,2480 10130,2800 10105,2825 9975,2825 9925,2875 9925,3150 9960,3185 J90.7@9960,3255
NetJ55_L15: J55.L15 J91.2 | length 1826.8
  Signal Layer 4 w10: J55.L15@9165.04,1599.84 9165,1599.8 9165,1230 9220,1175 9575,1175 9795,1395 9800,1390 9950,1390 10070,1510 10385,1510 10400,1525 J91.2@10400,1575
  Bottom Layer w10: J55.L15@9165.04,1599.84 J55.L15@9165.04,1599.84
NetJ55_L18: J55.L18 J94.2 | length 896.2
  Signal Layer 4 w10: J55.L18@9644.96,1599.84 9765.12,1720 9980,1720 10065,1635 10385,1635 10400,1650 J94.2@10400,1700
NetJ57_1: J57.1 R73.2 | length 93.5
  Bottom Layer w20: J57.1@5750,325 R73.2@5843.5,325
NetJ59_1: J59.1 R74.2 | length 93.5
  Bottom Layer w20: J59.1@5750,825 R74.2@5843.5,825
NetJ61_1: J61.1 R75.2 | length 93.5
  Bottom Layer w20: R75.2@10206.5,700 J61.1@10300,700
NetJ62_1: J62.1 R76.1 | length 93.5
  Bottom Layer w20: J62.1@5750,450 R76.1@5843.5,450
NetJ63_1: J63.1 R77.1 | length 93.5
  Bottom Layer w20: J63.1@5750,950 R77.1@5843.5,950
NetJ64_1: J64.1 R78.1 | length 93.5
  Bottom Layer w20: R78.1@10206.5,575 J64.1@10300,575
NetJ66_1: J66.1 R79.2 | length 93.5
  Bottom Layer w20: J66.1@5750,1700 R79.2@5843.5,1700
NetJ68_1: J68.1 R80.2 | length 93.5
  Bottom Layer w20: J68.1@5750,1200 R80.2@5843.5,1200
NetJ70_1: J70.1 R81.2 | length 93.5
  Bottom Layer w20: R81.2@10206.5,1325 J70.1@10300,1325
NetJ71_1: J71.1 R82.1 | length 93.5
  Bottom Layer w20: J71.1@5750,1575 R82.1@5843.5,1575
NetJ72_1: J72.1 R83.1 | length 93.5
  Bottom Layer w20: J72.1@5750,1075 R83.1@5843.5,1075
NetJ73_1: J73.1 R84.1 | length 93.5
  Bottom Layer w20: R84.1@10206.5,1450 J73.1@10300,1450
NetJ78_1: J78.1 R85.2 | length 93.5
  Bottom Layer w20: J78.1@5750,575 R85.2@5843.5,575
NetJ80_1: J80.1 R86.2 | length 93.5
  Bottom Layer w20: R86.2@10206.5,950 J80.1@10300,950
NetJ82_1: J82.1 R87.2 | length 93.5
  Bottom Layer w20: R87.2@10206.5,450 J82.1@10300,450
NetJ83_1: J83.1 R88.1 | length 93.5
  Bottom Layer w20: J83.1@5750,700 R88.1@5843.5,700
NetJ84_1: J84.1 R89.1 | length 88.5
  Bottom Layer w20: R89.1@10211.5,825 J84.1@10300,825
NetJ85_1: J85.1 R90.1 | length 93.5
  Bottom Layer w20: R90.1@10206.5,325 J85.1@10300,325
NetJ87_1: J87.1 R91.2 | length 93.5
  Bottom Layer w20: J87.1@5750,1450 R91.2@5843.5,1450
NetJ89_1: J89.1 R92.2 | length 93.5
  Bottom Layer w20: R92.2@10206.5,1075 J89.1@10300,1075
NetJ91_1: J91.1 R93.2 | length 93.5
  Bottom Layer w20: R93.2@10206.5,1575 J91.1@10300,1575
NetJ92_1: J92.1 R94.1 | length 93.5
  Bottom Layer w20: J92.1@5750,1325 R94.1@5843.5,1325
NetJ93_1: J93.1 R95.1 | length 93.5
  Bottom Layer w20: R95.1@10206.5,1200 J93.1@10300,1200
NetJ94_1: J94.1 R96.1 | length 93.5
  Bottom Layer w20: R96.1@10206.5,1700 J94.1@10300,1700
NetQ1_1: Q1.1 R98.1 | length 904.8
  Top Layer w20: Q1.1@11050,7056.65 11056.65,7050 11061.65,7055 v1(11100,7055) ; v1(11500,7380) R98.1@11573.5,7380
  Signal Layer 3 w20: v1(11100,7055) 11155,7000 11455,7000 11500,7045 v1(11500,7380)
NetQ2_1: Q2.1 R99.2 | length 1196.9
  Top Layer w20: Q2.1@10545,7056.65 10551.65,7050 10556.65,7055 v1(10600,7055) ; v1(11500,7450) R99.2@11573.5,7450
  Signal Layer 3 w20: v1(10600,7055) 10702.08,7157.08 11207.08,7157.08 v1(11500,7450)
NetQ3_1: Q3.1 R101.1 | length 947.3
  Top Layer w20: Q3.1@12900,7056.65 12901.65,7055 v1(12950,7055) ; v1(13375,7390) R101.1@13448.5,7390
  Signal Layer 3 w20: v1(12950,7055) 13005,7000 13350,7000 13375,7025 v1(13375,7390)
NetQ4_1: Q4.1 R102.1 | length 1216.9
  Top Layer w20: Q4.1@12400,7056.65 12401.65,7055 v1(12450,7055) ; v1(13375,7460) R102.1@13448.5,7460
  Signal Layer 3 w20: v1(12450,7055) 12545,7150 13065,7150 v1(13375,7460)
NetQ5_1: Q5.1 R19.2 R104.2 U9.6 | length 570
  Top Layer w8: R19.2@9703.62,7290 9775,7290 9800,7315 9800,7370 9840.32,7410.31 U9.6@9866.38,7410.31
  Top Layer w10: R104.2@9508.62,7458 9559.1,7458 9586.65,7430.45 9586.65,7368.35 9602.4,7352.6 Q5.1@9642.24,7352.6
  Top Layer w15: Q5.1@9642.24,7352.6 9682.4,7352.6 9703.62,7331.38 R19.2@9703.62,7290
NetQ5_3: Q5.3 R104.1 U10.2 | length 153.9
  Top Layer w10: U10.2@9461.38,7390.22 R104.1@9461.38,7458
  Top Layer w15: U10.2@9461.59,7390 Q5.3@9547.76,7390
NetQ6_1: Q6.1 R22.2 R105.2 U11.6 | length 565.5
  Top Layer w7: R22.2@9698.62,7640 9750,7640 9780,7670 9780,7700 9835.32,7755.31 U11.6@9856.38,7755.31
  Top Layer w10: R105.2@9508.62,7829 9559.46,7829 9589.02,7799.44 9589.02,7714.33 9600.75,7702.6 Q6.1@9637.24,7702.6
  Top Layer w20: Q6.1@9637.24,7702.6 9677.4,7702.6 9698.62,7681.38 R22.2@9698.62,7640
NetQ6_3: Q6.3 R105.1 U12.2 | length 154.9
  Top Layer w10: U12.2@9461.38,7740.22 R105.1@9461.38,7829
  Top Layer w20: U12.2@9476.59,7740 Q6.3@9542.76,7740
NetQ7_1: Q7.1 Q7.2 Q7.3 R35.2 R38.1 | length 160.9
  Top Layer w13: Q7.3@11247.2,3970.53 11247.2,4018.23 11258.98,4030 R38.1@11283.5,4030
  Top Layer w15: R38.1@11283.5,4030 11285,4031.5 R35.2@11285,4101.38
NetQ7_4: Q7.4 R34.2 | length 79.8
  Top Layer w12: R34.2@11200,4041.38 11200,4005 11221.61,3983.39 Q7.4@11221.61,3970.53
NetR2_2: R2.2 U2.1 | length 86.6
  Top Layer w15: R2.2@9460,6773.62 9460.61,6774.23 U2.1@9460.61,6860
NetR5_1: R5.1 R7.2 R8.2 U4.3 | length 366.1
  Top Layer w12: R5.1@9753.62,7015 9783.62,6985 9895,6985 9905.59,6974.41 U4.3@9905.59,6940.71 9905,6940.12 9905,6890 9898.62,6883.62 R8.2@9898.62,6835 R7.2@9898.62,6780
NetR11_2: R11.2 U7.5 | length 69
  Top Layer w10: U7.5@887.6,3701.61 890,3699.21 R11.2@890,3633.62
NetR18_1: R18.1 U1.8 | length 64.8
  Top Layer w10: R18.1@9970,6981.38 9971.61,6979.76 U1.8@9971.61,6917.2
NetR20_2: R20.2 U10.1 | length 85.8
  Top Layer w15: U10.1@9460.61,7290 R20.2@9546.38,7290
NetR23_2: R23.2 U12.1 | length 65.8
  Top Layer w20: U12.1@9475.61,7640 R23.2@9541.38,7640
NetR33_1: R33.1 T1.6 | length 156.4
  Top Layer w25: R33.1@10920,3685 10975,3685 11038.15,3748.15 T1.6@11038.15,3760.24
NetR34_1: R34.1 U13.5 | length 496.1
  Top Layer w10: U13.5@10794.37,3922.4 10794.37,3959.37 10810,3975 10975,3975 11088.62,4088.62 R34.1@11200,4088.62
NetR37_1: R37.1 U13.9 | length 80.1
  Top Layer w10: R37.1@10720,4171.38 10735.31,4156.06 U13.9@10735.31,4097.6
NetR41_2: R41.2 R45.2 U15.1 | length 122.5
  Top Layer w15: R41.2@10725,3333.62 10726.38,3335 R45.2@10781.38,3335 10780,3336.38 U15.1@10780,3400
NetR98_2: R98.2 R99.1 U3.5 | length 186.8
  Top Layer w20: R99.1@11636.5,7450 R98.2@11636.5,7380 11680,7380 11710,7410 U3.5@11740.86,7410
NetR101_2: R101.2 R102.2 U6.5 | length 184.7
  Top Layer w20: R102.2@13511.5,7460 R101.2@13511.5,7390 13555,7390 13580,7415 U6.5@13615.87,7415
OC_ALERT: J12.8 R3.2 TP3.1 U2.4 | length 8092.6
  Top Layer w20: R3.2@9023.62,6860 U2.4@9098.41,6860 9100,6858.41 v1(9100,6750)
  Signal Layer 7 w10: v1(9100,6750) 9100,4650 9175,4575 12275,4575 12500,4350 12500,2700 12400,2600 J12.8@12400,2500
  Bottom Layer w20: TP3.1@8750,6850 8850,6750 v1(9100,6750)
OSS: J8.9 J9.9 J10.1 J11.3 J12.2 TP14.1 | length 19537.9
  Signal Layer 7 w10: J8.9@300,4050 455,4050 905,4500 v1(7750,4500) ; v1(8100,4375) 12110,4375 12175,4310 v1(12175,3850) 12175,2775 12150,2750 11850,2750 11800,2700 J12.2@11800,2500 ; v1(8475,4575) J11.3@8475,6200 v1(8475,6650)
  Signal Layer 8 w10: v1(7750,4500) 7750,4450 7825,4375 v1(8100,4375) 8420,4375 8475,4430 v1(8475,4575)
  Bottom Layer w10: J10.1@8150,7600 8150,7430 8325,7255 8325,7000 TP14.1@8475,6850 v1(8475,6650) ; v1(12175,3850) J9.9@13700,3850
PG1: J12.9 R21.2 TP6.1 U10.4 | length 8509.3
  Top Layer w20: R21.2@9023.62,7290 U10.4@9098.41,7290 9100,7288.41 v1(9100,7200)
  Signal Layer 7 w10: v1(9100,7200) 9150,7150 9150,4700 9225,4625 12320,4625 12550,4395 12550,2650 12500,2600 J12.9@12500,2500
  Bottom Layer w20: TP6.1@8750,7125 9025,7125 v1(9100,7200)
PG2: J12.10 R24.2 TP7.1 U12.4 | length 8905.2
  Top Layer w20: R24.2@9023.62,7640 U12.4@9098.41,7640 9100,7638.41 v1(9100,7550)
  Signal Layer 7 w10: v1(9100,7550) 9200,7450 9200,4750 9275,4675 12360,4675 12600,4435 J12.10@12600,2500
  Bottom Layer w20: TP7.1@8750,7350 8950,7550 v1(9100,7550)
PSE_3.3V: C55.2 J11.9 J14.1 TP8.1 | length 1827.1
  Top Layer w20: J14.1@7550,7450 C55.2@7683.5,7450
  Top Layer w25: J14.1@7550,7450 7550,7530 7620,7600 TP8.1@7750,7600
  Signal Layer 7 w50: J14.1@7550,7450 7550,6830 7875,6505 J11.9@7875,6200
PSE_N1_A: J15.A11 J15.A16 J34.3 | length 5442
  Signal Layer 2 w25: J15.A11@1549.92,1254.96 J15.A11@1549.92,1254.96 1579.88,1225 1645,1225 1675,1255 1675,1715 1640,1750 1000,1750 900,1850 900,3420 930,3450 1405,3450 1450,3495 1450,4000 1500,4050 1650,4050 1675,4025 J34.3@1675,3950
  Signal Layer 6 w10: J15.A16@1537.32,349.84 1675,487.52 1675,1129.88 J15.A11@1549.92,1254.96
PSE_N1_B: J15.I11 J15.I16 J35.3 | length 4940.1
  Signal Layer 2 w25: J35.3@3125,3950 3125,4025 3100,4050 2925,4050 2900,4025 2900,3475 2925,3450 3130,3450 3150,3430 3150,2000 3450,1700 3825,1700 3850,1675 3850,1565 3800,1515 3705,1515 3670,1480 3670,1334.88 J15.I11@3749.92,1254.96
  Signal Layer 6 w10: J15.I16@3737.32,379.76 3650,467.09 3650,1155.04 J15.I11@3749.92,1254.96
PSE_N1_C: J15.F11 J15.F16 J36.3 | length 4976.9
  Top Layer w10: J15.F16@2655.04,1599.84 2775,1479.88 2775,1285 2805,1255 2910.12,1255 J15.F11@2910.16,1254.96
  Signal Layer 4 w25: J15.F11@2910.16,1254.96 3000,1344.8 3000,1450 2950,1500 2870,1500 2825,1545 2825,1700 2875,1750 3200,1750 3250,1800 3250,3400 3300,3450 3800,3450 4000,3650 4000,3850 4100,3950 4300,3950 4400,4050 4550,4050 4575,4025 J36.3@4575,3950
PSE_N1_D: J55.A11 J55.A16 J74.3 | length 5378.6
  Signal Layer 2 w25: J74.3@6025,3950 6025,4025 6000,4050 5850,4050 5825,4025 5825,3745 5550,3470 5550,1950 5600,1900 6150,1900 6300,1750 6630,1750 6680,1700 6680,1490 6640,1450 6640,1225 6615,1200 6564.88,1200 J55.A11@6509.92,1254.96
  Signal Layer 6 w10: J55.A16@6497.32,349.84 6625,477.52 6625,1139.88 J55.A11@6509.92,1254.96
PSE_N1_E: J55.I11 J55.I16 J75.3 | length 5487.5
  Signal Layer 2 w25: J75.3@7475,3950 7475,4025 7450,4050 7300,4050 7275,4025 7275,3475 7300,3450 7825,3450 7850,3425 7850,1950 7900,1900 8325,1900 8525,1700 8752.62,1700 8800,1652.62 8800,1525 8760,1485 8685,1485 8640,1440 8640,1324.88 J55.I11@8709.92,1254.96
  Signal Layer 6 w10: J55.I16@8697.32,379.76 8600,477.09 8600,1145.04 J55.I11@8709.92,1254.96
PSE_N1_F: J55.F11 J55.F16 J76.3 | length 4360.2
  Top Layer w10: J55.F16@7615.04,1599.84 7750,1464.88 7750,1280 7775,1255 7870.12,1255 J55.F11@7870.16,1254.96 J55.F11@7870.16,1254.96
  Signal Layer 4 w25: J55.F11@7870.16,1254.96 7935,1319.8 7935,1415 7800,1550 7800,1650 7925,1775 7925,3375 8000,3450 8250,3450 8300,3500 8300,3900 8350,3950 8650,3950 8750,4050 8900,4050 8925,4025 J76.3@8925,3950
PSE_N2_A: J15.A14 J15.A17 J34.7 | length 5758.6
  Signal Layer 2 w25: J15.A14@1599.92,1404.96 1600,1405.04 1600,1500 1625,1525 1625,1680 1605,1700 965,1700 850,1815 850,3470 880,3500 1365,3500 1400,3535 1400,4060 1440,4100 1800,4100 1875,4025 J34.7@1875,3950
  Signal Layer 6 w10: J15.A14@1599.92,1404.96 1675,1329.88 1675,1250 1750,1175 1850,1175 1900,1125 1900,550 1852.28,502.28 J15.A17@1852.28,319.92
PSE_N2_B: J15.I14 J15.I17 J35.7 | length 5461
  Top Layer w25: v1(3000,3500) 2825,3500 2800,3525 2800,4025 2875,4100 3300,4100 3325,4075 J35.7@3325,3950
  Signal Layer 2 w25: v1(3000,3500) 3175,3500 3200,3475 3200,2035 3485,1750 3875,1750 3900,1725 3900,1505.04 J15.I14@3799.92,1404.96
  Signal Layer 6 w10: J15.I14@3799.92,1404.96 3849.96,1404.96 3850,1405 3875,1380 3875,497.21 J15.I17@4052.28,319.92
PSE_N2_C: J15.F14 J15.F17 J36.7 | length 4819.4
  Signal Layer 4 w25: J15.F14@2860.16,1404.96 2750,1515.12 2750,1750 2800,1800 3100,1800 3175,1875 3175,3475 3200,3500 3750,3500 3950,3700 3950,3925 4125,4100 4750,4100 4775,4075 J36.7@4775,3950
  Bottom Layer w10: J15.F14@2860.16,1404.96 2860.16,1525.04 J15.F17@2934.96,1599.84
PSE_N2_D: J55.A14 J55.A17 J74.7 | length 5618.8
  Signal Layer 2 w25: J74.7@6225,3950 6225,4075 6200,4100 5800,4100 5775,4075 5775,3765 5500,3490 5500,1900 5550,1850 6100,1850 6250,1700 6585,1700 6625,1660 6625,1540 6559.92,1474.92 J55.A14@6559.92,1404.96
  Signal Layer 6 w10: J55.A14@6559.92,1404.96 6559.96,1405 6625,1405 6660,1370 6660,472.2 J55.A17@6812.28,319.92
PSE_N2_E: J55.I14 J55.I17 J75.7 | length 5986.1
  Top Layer w25: v1(7350,3525) 7250,3525 7225,3550 7225,4075 7250,4100 7650,4100 7675,4075 J75.7@7675,3950
  Signal Layer 2 w25: v1(7350,3525) 7850,3525 7900,3475 7900,2000 7950,1950 8375,1950 8575,1750 8850,1750 8875,1725 8875,1520.04 J55.I14@8759.92,1404.96
  Signal Layer 6 w10: J55.I14@8759.92,1404.96 8824.96,1404.96 8825,1405 8850,1380 8850,482.2 J55.I17@9012.28,319.92
PSE_N2_F: J55.F14 J55.F17 J76.7 | length 4232.1
  Signal Layer 4 w25: J55.F14@7820.16,1404.96 7725,1500.12 7725,1700 7875,1850 7875,3450 7950,3525 8200,3525 8250,3575 8250,3925 8325,4000 8600,4000 8700,4100 9100,4100 9125,4075 J76.7@9125,3950
  Bottom Layer w10: J55.F14@7820.16,1404.96 7820.16,1525.04 J55.F17@7894.96,1599.84
PSE_N3_A: J15.C11 J15.C16 J34.11 | length 5827.8
  Top Layer w25: v1(1550,3625) 1300,3625 1275,3650 1275,4025 1350,4100 2030,4100 2075,4055 J34.11@2075,3950
  Signal Layer 2 w25: v1(1550,3625) 1625,3625 1650,3600 1650,1925 1675,1900 2245,1900 2275,1870 2275,1520 2235,1480 2235,1230 2205,1200 2154.88,1200 J15.C11@2099.92,1254.96
  Signal Layer 6 w10: J15.C16@2087.32,379.76 2000,467.09 2000,1155.04 J15.C11@2099.92,1254.96
PSE_N3_B: J15.K11 J15.K16 J35.11 | length 4965.7
  Signal Layer 2 w25: J35.11@3525,3950 3525,4075 3550,4100 3950,4100 3975,4075 3975,1800 4025,1750 4425,1750 4450,1725 4450,1490 4425,1465 4425,1245 4405,1225 4329.88,1225 J15.K11@4299.92,1254.96
  Signal Layer 6 w10: J15.K16@4287.32,379.76 4200,467.09 4200,1155.04 J15.K11@4299.92,1254.96
PSE_N3_C: J15.H11 J15.H16 J36.11 | length 4983.4
  Top Layer w10: J15.H16@3205.04,1599.84 3325,1479.88 3325,1280 3350,1255 3460.12,1255 J15.H11@3460.16,1254.96
  Top Layer w25: v1(4275,3750) 4275,4050 4325,4100 4950,4100 4975,4075 J36.11@4975,3950
  Signal Layer 4 w25: J15.H11@3460.16,1254.96 3504.96,1254.96 3555,1305 3555,1370 3400,1525 3400,1800 3495,1895 3950,1895 4000,1945 4000,3400 4050,3450 4150,3450 4275,3575 v1(4275,3750)
PSE_N3_D: J55.C11 J55.C16 J74.11 | length 6058
  Top Layer w25: v1(5775,3450) 5775,4075 5800,4100 6400,4100 6425,4075 J74.11@6425,3950
  Signal Layer 2 w25: v1(5775,3450) 6255,3450 6305,3400 6305,1920 6375,1850 6800,1850 6900,1750 7200,1750 7225,1725 7225,1460 7185,1420 7185,1255 7145,1215 7099.88,1215 J55.C11@7059.92,1254.96
  Signal Layer 6 w10: J55.C16@7047.32,379.76 6950,477.09 6950,1145.04 J55.C11@7059.92,1254.96
PSE_N3_E: J55.K11 J55.K16 J75.11 | length 5452.9
  Signal Layer 2 w25: J75.11@7875,3950 7875,4075 7900,4100 8200,4100 8250,4050 8250,3550 8300,3500 8650,3500 8675,3475 8675,1925 8750,1850 8950,1850 9050,1750 9375,1750 9425,1700 9425,1440 9390,1405 9390,1260 9355,1225 9289.88,1225 J55.K11@9259.92,1254.96
  Signal Layer 6 w10: J55.K16@9247.32,379.76 9150,477.09 9150,1145.04 J55.K11@9259.92,1254.96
